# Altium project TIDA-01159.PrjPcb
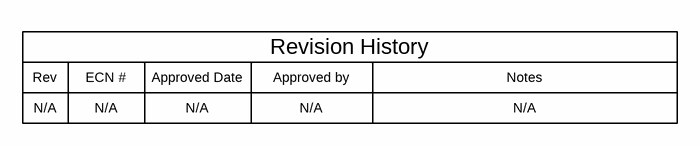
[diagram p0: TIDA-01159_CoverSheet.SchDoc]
CopyrightYear: 2016; EVM_Orderable: N/A; PCB_Layout: Akshay Labhe; PCB_Rev: E1; PRJ_Customer: Public Release; PRJ_Engineer: Ramkumar S; PRJ_Number: TIDA-01159; PRJ_Title: Gate Drive Solution; SCH_Rev: E1; TechSupport: http://www.ti.com/support; TID: TIDA-01159
3 sheets, 35 parts. Net scope: global (net labels, ports and power ports of the same name join across sheets).
Board file: TIDA-01159.PcbDoc
Sheets:
  TIDA-01159_CoverSheet.SchDoc
  TIDA-01159_Sheet1.SchDoc
  TIDA-01159_Hardware.SchDoc

## Sheet TIDA-01159_CoverSheet.SchDoc
size 431 x 279 mm; Date: Not shown in title block; ApprovedBy: Not shown in title block; CheckedBy: Not shown in title block; Author: Not shown in title block; CompanyName: Not shown in title block; DrawnBy: Ramkumar S; Engineer: Not shown in title block; Organization: Not shown in title block; Address1: Not shown in title block; Address2: Not shown in title block; Address3: Not shown in title block; Address4: Not shown in title block; DocumentNumber: 1; Revision: Use project parameter SCH_Rev; SheetNumber: 1; SheetTotal: 3; PageSetup: Record=PageOptions¦CenterHorizontal=True¦CenterVertical=True¦PrintScale=1.00¦XCorrection=1.00¦YCorrection=1.00¦PrintKind=0¦BorderSize=5000000¦LeftOffset=0¦BottomOffset=0¦Orientation=2¦PaperLength=1000¦PaperWidth=1000¦Scale=100¦PaperSource=15¦PrintQuality=600¦MediaType=1¦DitherType=10¦PaperKind=Letter¦PrintScaleMode=1

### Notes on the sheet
- Rev
- N/A
- ECN #
- Approved Date
- Approved by
- Revision History
- Notes

## Sheet TIDA-01159_Sheet1.SchDoc
size 431 x 279 mm; Date: Not shown in title block; ApprovedBy: Not shown in title block; CheckedBy: Not shown in title block; Author: Not shown in title block; CompanyName: Not shown in title block; DrawnBy: Ramkumar S; Engineer: Not shown in title block; Organization: Not shown in title block; Address1: Not shown in title block; Address2: Not shown in title block; Address3: Not shown in title block; Address4: Not shown in title block; DocumentNumber: 1; Revision: Use project parameter SCH_Rev; SheetNumber: 2; SheetTotal: 3; PageSetup: Record=PageOptions¦CenterHorizontal=True¦CenterVertical=True¦PrintScale=1.00¦XCorrection=1.00¦YCorrection=1.00¦PrintKind=0¦BorderSize=5000000¦LeftOffset=0¦BottomOffset=0¦Orientation=2¦PaperLength=1000¦PaperWidth=1000¦Scale=100¦PaperSource=15¦PrintQuality=600¦MediaType=1¦DitherType=10¦PaperKind=Letter¦PrintScaleMode=1
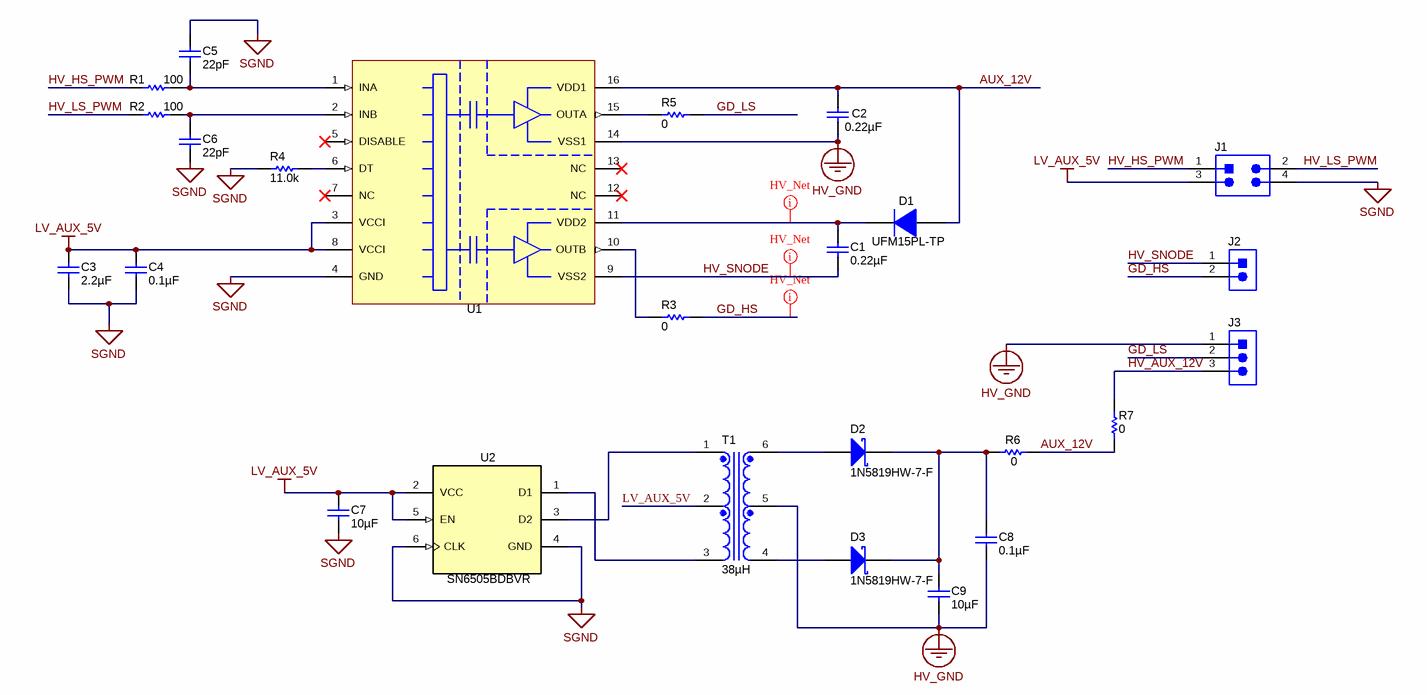
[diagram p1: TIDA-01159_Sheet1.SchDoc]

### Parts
C1  ValueDisplayed: 0.22µF  [1206]  (hidden comment: CGA5L3X7T2E224K160AE)
C2  ValueDisplayed: 0.22µF  [1206]  (hidden comment: CGA5L3X7T2E224K160AE)
C3  ValueDisplayed: 2.2µF  [0603]  (hidden comment: 885012106018)
C4  ValueDisplayed: 0.1µF  [0603]  (hidden comment: C0603X104K3RACTU)
C5  ValueDisplayed: 22pF  [0603]  (hidden comment: 06035A220JAT2A)
C6  ValueDisplayed: 22pF  [0603]  (hidden comment: 06035A220JAT2A)
C7  ValueDisplayed: 10µF  [0805_145]  (hidden comment: EMK212BB7106MG-T)
C8  ValueDisplayed: 0.1µF  [0603]  (hidden comment: GRM188R61C104KA01D)
C9  ValueDisplayed: 10µF  [0805_145]  (hidden comment: EMK212BB7106MG-T)
D1  UFM15PL-TP  [SOD-123FL]
D2  1N5819HW-7-F  [SOD-123]
D3  1N5819HW-7-F  [SOD-123]
J1  61300421021  [Wurth_61300421021]  (value not drawn)
J2  TSW-102-08-G-S-RA  [TSW-102-08-G-S-RA]  (value not drawn)
J3  TSW-103-08-G-S-RA  [TSW-103-08-G-S-RA]  (value not drawn)
R1  ValueDisplayed: 100  [0603]  (hidden comment: CRCW0603100RFKEA)
R2  ValueDisplayed: 100  [0603]  (hidden comment: CRCW0603100RFKEA)
R3  ValueDisplayed: 0  [0805_HV]  (hidden comment: CRCW08050000Z0EA)
R4  ValueDisplayed: 11.0k  [0603]  (hidden comment: RC0603FR-0711KL)
R5  ValueDisplayed: 0  [0805_HV]  (hidden comment: CRCW08050000Z0EA)
R6  ValueDisplayed: 0  [0603]  (hidden comment: CRCW06030000Z0EA)
R7  ValueDisplayed: 0  [0603]  (hidden comment: CRCW06030000Z0EA)
T1  ValueDisplayed: 38µH  [Wurth_750342879]  (hidden comment: 750343341)
U1  UCC21520DW  [DW0016A_N]  (value not drawn)
U2  SN6505BDBVR  [DBV0006A_N]

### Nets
HV_GND: C2.2 C8.2 C9.2 J3.1 T1.5 U1.14(VSS1)
LV_AUX_5V: C3.2 C4.1 C7.1 J1.3 T1.2 U1.3(VCCI) U1.8(VCCI) U2.2(VCC) U2.5(EN)
SGND: C3.1 C4.2 C5.2 C6.2 C7.2 J1.4 R4.1 U1.4(GND) U2.4(GND) U2.6(CLK)
AUX_12V: C2.1 D1.2(A) R6.2 R7.1 U1.16(VDD1)
GD_HS: J2.2 R3.2
GD_LS: J3.2 R5.2
HV_AUX_12V: J3.3 R7.2
HV_HS_PWM: J1.1 R1.1
HV_LS_PWM: J1.2 R2.1
HV_SNODE: C1.2 J2.1 U1.9(VSS2)
NetC1_1: C1.1 D1.1(K) U1.11(VDD2)
NetC5_1: C5.1 R1.2 U1.1(INA)
NetC6_1: C6.1 R2.2 U1.2(INB)
NetC8_1: C8.1 C9.1 D2.1(K) D3.1(K) R6.1
NetD2_2: D2.2(A) T1.6
NetD3_2: D3.2(A) T1.4
NetR3_1: R3.1 U1.10(OUTB)
NetR4_2: R4.2 U1.6(DT)
NetR5_1: R5.1 U1.15(OUTA)
NetT1_1: T1.1 U2.3(D2)
NetT1_3: T1.3 U2.1(D1)

Not connected (* = marked no-connect by the designer): U1 5(DISABLE)* 7(NC)* 12(NC)* 13(NC)*

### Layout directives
mark named HV_Net: GD_HS, HV_SNODE, NetC1_1

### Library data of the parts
C1 C2 = CGA5L3X7T2E224K160AE: CAP, CERM, 0.22 µF, 250 V, +/- 10%, X7T, 1206; Manufacturer: TDK; Polarized: N; CompType: Capacitor; Value: 0.22uF; U/M: EA; Cap_F: 0.00000022; Tolerance_%: 10; Value1: Unknown; VDC_V: 250; Value2: 250V; TaMin_C: -55; TaMax_C: 125
C3 = 885012106018: CAP, CERM, 2.2 µF, 16 V, +/- 20%, X5R, 0603; Manufacturer: Wurth Elektronik; Polarized: N; CompType: Capacitor; Value: 2.2uF; U/M: EA; Cap_F: 0.0000022; Tolerance_%: 20; Value1: Unknown; VDC_V: 16; Value2: 16V; TaMin_C: -55; TaMax_C: 85; SizeArea_mm2: 1.28; SizeAreaWB_mm2: 4.68; SizeX_mm: 1.6; SizeY_mm: 0.8; SizeZ_mm: 1; AEC Category: Q200
C4 = C0603X104K3RACTU: CAP, CERM, 0.1 µF, 25 V, +/- 10%, X7R, 0603; Manufacturer: Kemet; Polarized: N; CompType: Capacitor; Value: 0.1uF; U/M: EA; Cap_F: 0.0000001; Tolerance_%: 10; Value1: Unknown; VDC_V: 25; Value2: 25V; TaMin_C: -55; TaMax_C: 125
C5 C6 = 06035A220JAT2A: CAP, CERM, 22 pF, 50 V, +/- 5%, C0G/NP0, 0603; Manufacturer: AVX; Polarized: N; CompType: Capacitor; Value: 22pF; U/M: EA; Cap_F: 0.000000000022; Tolerance_%: 5; ESR_ohm: 0.259; Value1: 0.259 ohm; VDC_V: 50; Value2: 50V; TaMin_C: -55; TaMax_C: 125; SizeArea_mm2: 1.28; SizeAreaWB_mm2: 4.68; SizeX_mm: 1.6; SizeY_mm: 0.8; SizeZ_mm: 1; AEC Category: Q200
C7 C9 = EMK212BB7106MG-T: CAP, CERM, 10 µF, 16 V, +/- 20%, X7R, 0805; Manufacturer: Taiyo Yuden; Polarized: N; CompType: Capacitor; Value: 10uF; U/M: EA; Cap_F: 0.00001; Tolerance_%: 20; Value1: Unknown; VDC_V: 16; Value2: 16V; TaMin_C: -55; TaMax_C: 125; Cap_Case: 0805
C8 = GRM188R61C104KA01D: CAP, CERM, 0.1 µF, 16 V, +/- 10%, X5R, 0603; Manufacturer: MuRata; Polarized: N; CompType: Capacitor; Value: 0.1uF; U/M: EA; Cap_F: 0.0000001; Tolerance_%: 10; Value1: Unknown; VDC_V: 16; Value2: 16V; TaMin_C: -55; TaMax_C: 85
D1 = UFM15PL-TP: Diode, Ultrafast, 600 V, 1 A, SOD-123FL; Manufacturer: Micro Commercial Components; U/M: EA; Vf_V: 1.7; Value: 600V; Value1: 1A; Value2: 1.7V; Io_A: 1; Vr_V: 600; TJmax_C: 150; SizeAreaWB_mm2: 13.44; SizeArea_mm2: 6.84; SizeX_mm: 3.8; SizeY_mm: 1.8; AEC Category: Q101; AEC Qualified: N
D2 D3 = 1N5819HW-7-F: Diode, Schottky, 40 V, 1 A, SOD-123; Manufacturer: Diodes Inc.; U/M: EA; Vf_V: 0.45; Value: 40V; Value1: 1A; Value2: 0.45V; Io_A: 1; Vr_V: 40; TJmax_C: 125; SizeAreaWB_mm2: 13.095; SizeArea_mm2: 6.545; SizeX_mm: 3.85; SizeY_mm: 1.7; SizeZ_mm: 1.35; AEC Category: Q101
J1 = 61300421021: Header, 2.54mm, 2x2, Gold, R/A, TH; Manufacturer: Wurth Elektronik; SymbolCreator: a0412235; Pitch_mm: 2.54; Gender: Male; Shrouded: N; Row_Count: 2
J2 = TSW-102-08-G-S-RA: Header, 100mil, 2x1, Gold, R/A, TH; Manufacturer: Samtec; SymbolCreator: a0412235; Pitch_mm: 2.54; Gender: Male; Shrouded: N; Row_Count: 1; Current_A: 6.3; Voltage_V: 550; Cert_CSA: Y
J3 = TSW-103-08-G-S-RA: Header, 100mil, 3x1, Gold, R/A, TH; Manufacturer: Samtec; SymbolCreator: a0799628; Pitch_mm: 2.54; Gender: Male; Shrouded: N; Row_Count: 1; Current_A: 6.3; Voltage_V: 550; Cert_CSA: Y
R1 R2 = CRCW0603100RFKEA: RES, 100, 1%, 0.1 W, 0603; Manufacturer: Vishay-Dale; CompType: Resistor; Value: 100; Value_Code: 100R; Tolerance_%: 1; Power_W: 0.1; Value2: 0.1W; VDC_V: 75; TempCo: 100 ppm/C; EIA_Code: E96; U/M: EA
R3 R5 = CRCW08050000Z0EA: RES, 0, 5%, 0.125 W, 0805; Manufacturer: Vishay-Dale; CompType: Resistor; Value: 0; Value_Code: 0000; Tolerance_%: 5; Power_W: 0.125; Value2: 0.125W; VDC_V: 150; TempCo: 200 ppm/C; EIA_Code: E24; U/M: EA; AEC Category: Q200
R4 = RC0603FR-0711KL: RES, 11.0 k, 1%, 0.1 W, 0603; Manufacturer: Yageo America; CompType: Resistor; Value: 11.0k; Res_ohm: 11000; Value_Code: 11k0; Tolerance_%: 1; Power_W: 0.1; Value2: 0.1W; VDC_V: 150; TempCo: 200 ppm/C; EIA_Code: E96; U/M: EA
R6 R7 = CRCW06030000Z0EA: RES, 0, 5%, 0.1 W, 0603; Manufacturer: Vishay-Dale; CompType: Resistor; Value: 0; Value_Code: 0000; Tolerance_%: 5; Power_W: 0.1; Value2: 0.1W; VDC_V: 75; TempCo: 200 ppm/C; EIA_Code: E24; U/M: EA
T1 = 750342879: Transformer, 50 uH, SMT; Manufacturer: Wurth Elektronik; SymbolCreator: Altium; Value: 38uH; Lp: 38
U1 = UCC21520DW: 4A/6A, 5KVrms Dual Isolated-channel Universal Gate Driver, DW0016A; Manufacturer: Texas Instruments; SymbolCreator: a0799628; CompType: IC; U/M: EA
U2 = SN6505BDBVR: LOW-NOISE 1A TRANSFORMER DRIVERS FOR ISOLATED POWER SUPPLIES, DBV0006A; Alternate PartNumber: SN6505BDBVT; Manufacturer: Texas Instruments; SymbolCreator: Altium; SizeArea_mm2: 8.12; SizeAreaWB_mm2: 14.82; SizeX_mm: 2.8; SizeY_mm: 2.9; SizeZ_mm: 1.45; CompType: IC; U/M: EA

## Sheet TIDA-01159_Hardware.SchDoc
size 431 x 279 mm; Date: Not shown in title block; ApprovedBy: Not shown in title block; CheckedBy: Not shown in title block; Author: Not shown in title block; CompanyName: Not shown in title block; Engineer: Not shown in title block; Organization: Not shown in title block; Address1: Not shown in title block; Address2: Not shown in title block; Address3: Not shown in title block; Address4: Not shown in title block; DocumentNumber: 1; Revision: Use project parameter SCH_Rev; SheetNumber: 3; SheetTotal: 3; PageSetup: Record=PageOptions¦CenterHorizontal=True¦CenterVertical=True¦PrintScale=1.00¦XCorrection=1.00¦YCorrection=1.00¦PrintKind=0¦BorderSize=5000000¦LeftOffset=0¦BottomOffset=0¦Orientation=2¦PaperLength=1000¦PaperWidth=1000¦Scale=100¦PaperSource=15¦PrintQuality=600¦MediaType=1¦DitherType=10¦PaperKind=Letter¦PrintScaleMode=1
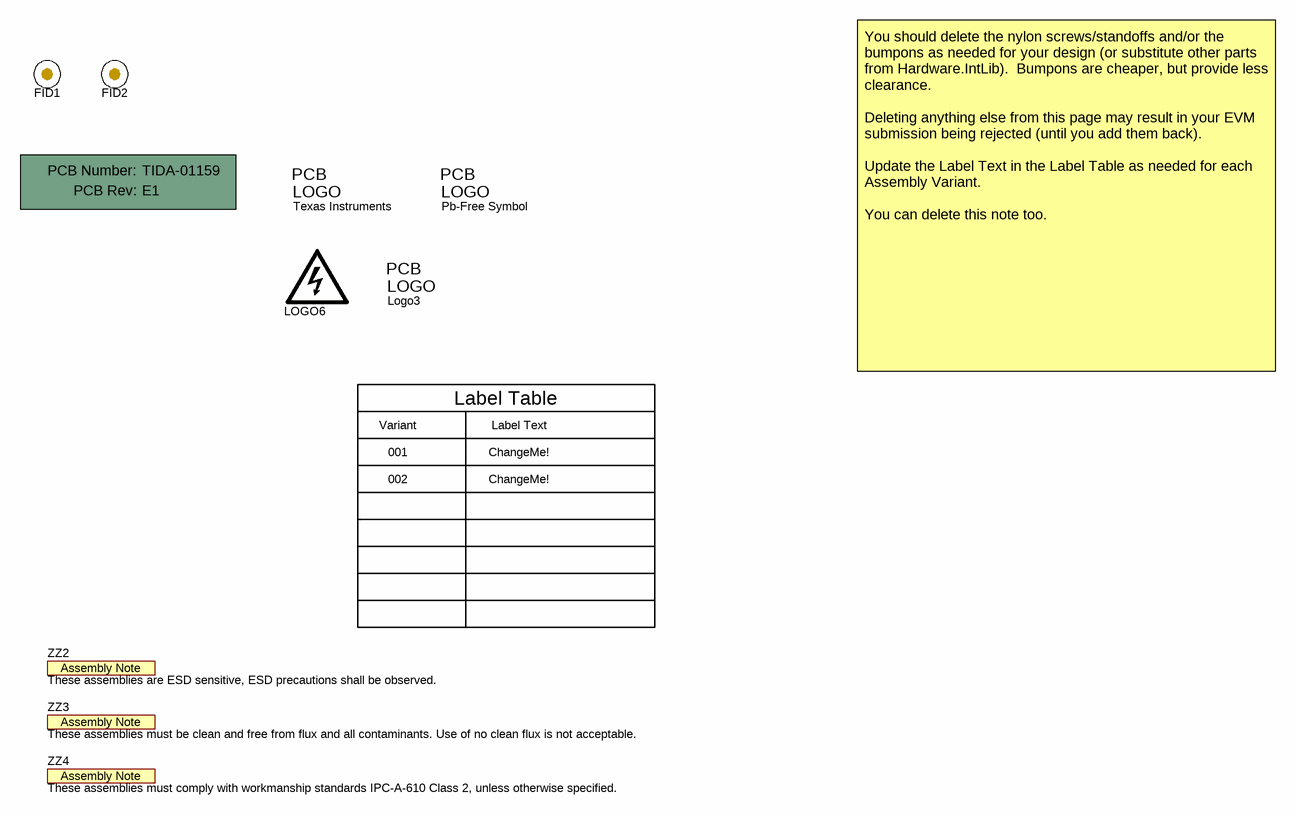
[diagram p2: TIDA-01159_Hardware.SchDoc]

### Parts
!PCB  Printed Circuit Board  (value not drawn)  (mechanical)
FID1  Fiducial  [Fiducial10-20]  (value not drawn)
FID2  Fiducial  [Fiducial10-20]  (value not drawn)
Logo1  Texas Instruments  [TI_Symbol_Overlay_Small]  (no BOM)
Logo2  Pb-Free Symbol  [Pb-Free_Overlay_Small]  (no BOM)
Logo3  ESD Susceptible  [ESD_Overlay_Small]  (value not drawn)  (no BOM)
LOGO6  DANGER HIGH VOLTAGE  [IEC_HighVoltage_Small]  (value not drawn)  (no BOM)
ZZ2  These assemblies are ESD sensitive, ESD precautions shall be observed.  [AssemblyNote]  (no BOM)
ZZ3  These assemblies must be clean and free from flux and all contaminants. Use of no clean flux is not acceptable.  [AssemblyNote]  (no BOM)
ZZ4  These assemblies must comply with workmanship standards IPC-A-610 Class 2, unless otherwise specified.  [AssemblyNote]  (no BOM)

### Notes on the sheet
- Variant
- Label Table
- Label Text
- You should delete the nylon screws/standoffs and/or the bumpons as needed for your design (or substitute other parts from Hardware.IntLib).  Bumpons are cheaper, but provide less clearance.
  Deleting anything else from this page may result in your EVM submission being rejected (until you add them back).
  Update the Label Text in the Label Table as needed for each Assembly Variant.
  You can delete this note too.
- 001
- 002
- ChangeMe!

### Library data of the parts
!PCB = PCB: Manufacturer: Any; PartNumber: TIDA-01159; SymbolCreator: a0412235
FID1 FID2 = Fiducial: Fiducial mark.  There is nothing to buy or mount.; SymbolCreator: codlsc
Logo1 = TI_Logo: Texas Instrument Corporate Signature; SymbolCreator: codlsc
Logo2 = Pb-Free: SymbolCreator: a0412235
Logo3 = ESD_Susceptible: ESD Susceptible Symbol; SymbolCreator: a0412235
LOGO6 = IEC_HighVoltage: IEC 61010-1 High Voltage Warning; SymbolCreator: a0412235
ZZ2-ZZ4 = AssemblyNote: SymbolCreator: codlsc

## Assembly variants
001: not fitted FID1 FID2 FID3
